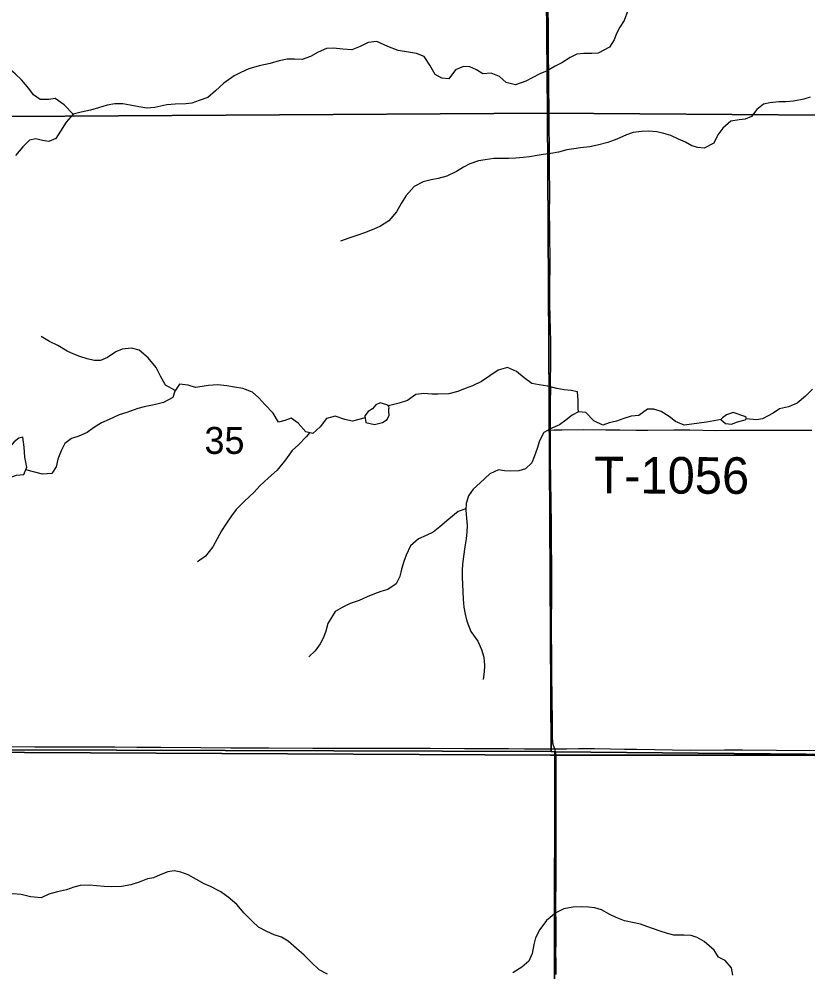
# Model space of a CAD drawing. Extents: x 1874609 to 2204689, y 815661 to 1281160.
# Drawn here: x 2003233 to 2009707, y 1055304 to 1063119 of the extents above; entities that cross this region are included whole.
import ezdxf

# ---------------------------------------------------------------- set-up
doc = ezdxf.new("R2010")
doc.units = 0
for name, color, linetype in [('GM_X_Minor_Lake', 7, 'Continuous'), ('GM_X_Minor_River', 7, 'Continuous'), ('GM_X_Section', 7, 'Continuous'), ('GM_X_Section_Text', 7, 'Continuous'), ('GM_X_Township', 7, 'Continuous'), ('GM_X_Township_Road', 7, 'Continuous'), ('GM_X_Township_Road_Text', 7, 'Continuous')]:
    doc.layers.add(name, color=color, linetype=linetype)

msp = doc.modelspace()

# ---------------------------------------------------------------- linework, layer by layer
at = {"layer": 'GM_X_Minor_Lake'}
for points in [[(2006250.7, 1059956.6), (2006196.4, 1059970.3), (2006160.4, 1059956), (2006132.6, 1059923.6), (2006098.7, 1059901.3), (2006070.9, 1059865), (2006079.4, 1059810.8), (2006149.7, 1059795.3), (2006215.8, 1059809.9), (2006253.7, 1059836.2), (2006269.5, 1059870.5), (2006269.2, 1059900.6)], [(2006269.2, 1059900.6), (2006267.5, 1059921.5), (2006269.5, 1059931.6), (2006268.5, 1059941.8), (2006262.4, 1059950.4), (2006250.7, 1059956.6)], [(2009190.1, 1059860.1), (2009093.6, 1059891.4), (2009037.6, 1059873), (2009005.7, 1059848.6), (2008993.7, 1059834.5), (2009030.1, 1059802.7), (2009080.3, 1059797), (2009128.3, 1059815.4), (2009192.4, 1059832)], [(2009192.4, 1059832), (2009200.8, 1059839.4), (2009201.1, 1059845.6), (2009200.1, 1059850.8), (2009190.1, 1059860.1)], [(2003061.7, 1059315.1), (2003136.6, 1059351.4), (2003212.6, 1059378), (2003272.7, 1059384.5), (2003298.3, 1059444.9), (2003279.5, 1059527.1), (2003274.9, 1059607.3), (2003264.2, 1059689.6), (2003232.1, 1059681.3), (2003194.2, 1059652.9), (2003160.5, 1059612.5), (2003094.2, 1059559.3), (2003053.8, 1059537.5)]]:
    msp.add_lwpolyline(points, dxfattribs=at)
at = {"layer": 'GM_X_Minor_River'}
for points in [[(2008229.8, 1063189), (2008200.4, 1063108.5), (2008164.7, 1063052), (2008137.1, 1063001.6), (2008117.4, 1062949.3), (2008077.8, 1062888.8), (2007986, 1062839.9), (2007933.8, 1062837.5), (2007867.6, 1062837), (2007809.5, 1062832.6), (2007755.6, 1062804.1), (2007687.7, 1062761.4), (2007631.8, 1062732.9), (2007567.9, 1062694.3), (2007508, 1062669.8), (2007444, 1062637.2), (2007392.1, 1062610.7), (2007306.1, 1062579.9), (2007231.7, 1062599.5), (2007175.2, 1062649.2), (2007108.7, 1062676.8), (2007038.6, 1062670.3), (2006986.1, 1062704), (2006931.8, 1062727.7), (2006879.6, 1062731.3), (2006815.6, 1062702.8), (2006760.1, 1062630.1), (2006703.9, 1062633.7), (2006647.5, 1062663.4), (2006604.7, 1062741.3), (2006558, 1062813.2), (2006495.6, 1062836.9), (2006429.3, 1062848.4), (2006344.9, 1062861.8), (2006258.4, 1062893.3), (2006169.8, 1062934.8), (2006097.7, 1062928.3), (2006031.8, 1062893.6), (2005963.8, 1062867), (2005889.5, 1062872.5), (2005813.2, 1062882), (2005757.1, 1062877.6), (2005689.2, 1062846.9), (2005625.2, 1062812.3), (2005557.2, 1062787.8), (2005495, 1062791.3), (2005432.9, 1062790.8), (2005366.8, 1062776.3), (2005294.7, 1062755.7), (2005202.6, 1062734.9), (2005118.6, 1062712.2), (2005052.6, 1062681.6), (2004998.7, 1062653.1), (2004915, 1062594.3), (2004845.3, 1062529.6), (2004781.5, 1062476.9), (2004711.6, 1062450.3), (2004651.6, 1062429.8), (2004601.4, 1062425.4), (2004515.2, 1062420.7), (2004447.1, 1062416.2), (2004346.9, 1062395.4), (2004280.8, 1062388.9), (2004216.5, 1062400.4), (2004146.2, 1062413.9), (2004083.9, 1062423.5), (2004019.7, 1062423.1), (2003955.6, 1062412.5), (2003885.6, 1062391.9), (2003819.6, 1062371.4), (2003743.5, 1062356.8), (2003677.4, 1062340.2), (2003619.8, 1062273.5), (2003574.3, 1062200.9), (2003534.7, 1062140.4), (2003476.7, 1062113.9), (2003424.5, 1062123.6), (2003370.2, 1062137.2), (2003318.1, 1062126.8), (2003264.5, 1062070.2), (2003204.9, 1061999.5)], [(2003677.4, 1062340.2), (2003604.6, 1062415.9), (2003529.9, 1062467.6), (2003477.9, 1062459.2), (2003407.7, 1062458.6), (2003351.2, 1062498.4), (2003314.6, 1062550.3), (2003253.9, 1062620.1), (2003201.3, 1062669.9), (2003142.7, 1062719.6), (2003064.2, 1062755.2)], [(2009726.1, 1062479.5), (2009674, 1062463), (2009589.9, 1062446.3), (2009525.8, 1062441.9), (2009469.6, 1062439.4), (2009395.5, 1062432.9), (2009341.4, 1062420.4), (2009287.6, 1062377.9), (2009244, 1062319.3), (2009192, 1062298.9), (2009141.9, 1062292.5), (2009075.8, 1062282), (2009008, 1062225.3), (2008968.4, 1062168.8), (2008934.8, 1062102.3), (2008855, 1062059.5), (2008804.8, 1062065.2), (2008754.5, 1062080.9), (2008702.1, 1062108.6), (2008645.7, 1062134.2), (2008581.3, 1062163.9), (2008525, 1062181.5), (2008466.7, 1062195.1), (2008398.5, 1062198.7), (2008340.3, 1062198.2), (2008272.2, 1062187.7), (2008218.2, 1062169.2), (2008138.2, 1062134.5), (2008064.2, 1062107.9), (2007980.2, 1062085.1), (2007916.1, 1062072.6), (2007842, 1062062), (2007785.9, 1062055.6), (2007729.8, 1062047.2), (2007659.7, 1062028.6), (2007597.6, 1062016.1), (2007535.5, 1062007.6), (2007485.4, 1061999.2), (2007421.3, 1061988.7), (2007371.2, 1061984.3), (2007309.1, 1061977.8), (2007248.9, 1061975.3), (2007184.7, 1061974.9), (2007128.6, 1061976.5), (2007058.4, 1061965.9), (2007004.4, 1061955.5), (2006932.4, 1061930.8), (2006880.4, 1061904.4), (2006822.5, 1061869.8), (2006744.6, 1061831.1), (2006672.6, 1061812.5), (2006616.5, 1061802), (2006548.5, 1061783.5), (2006476.6, 1061744.8), (2006409, 1061672), (2006369.4, 1061607.5), (2006329.8, 1061539), (2006268.3, 1061464.2), (2006200.5, 1061419.6), (2006144.5, 1061395.1), (2006068.5, 1061366.4), (2006004.5, 1061343.9), (2005938.5, 1061323.3)], [(2005938.5, 1061323.3), (2005872.5, 1061296.7)], [(2004515.5, 1060072.5), (2004434, 1060117.8), (2004393.3, 1060189.7), (2004358.6, 1060261.7), (2004293.8, 1060339.5), (2004219, 1060403.2), (2004156.7, 1060420.8), (2004080.6, 1060412.2), (2004026.6, 1060389.7), (2003958.8, 1060343.1), (2003902.8, 1060318.6), (2003850.7, 1060318.2), (2003792.4, 1060333.8), (2003732, 1060351.4), (2003681.7, 1060371.1), (2003629.4, 1060396.8), (2003552.8, 1060442.4), (2003484.3, 1060476), (2003413.7, 1060515.6)], [(2007823.8, 1059898.1), (2007821.5, 1059928.2), (2007821, 1059990.4), (2007816.4, 1060060.6), (2007764.2, 1060072.3), (2007706, 1060077.9), (2007645.7, 1060089.5), (2007573.3, 1060107), (2007501, 1060120.5), (2007442.7, 1060130.1), (2007378.2, 1060175.8), (2007315.6, 1060229.5), (2007241.1, 1060261.1), (2007165, 1060238.4), (2007097.2, 1060191.8), (2007029.4, 1060147.1), (2006955.5, 1060110.4), (2006895.5, 1060089.9), (2006833.5, 1060063.3), (2006759.4, 1060046.8), (2006671.2, 1060044.1), (2006621.1, 1060043.7), (2006554.8, 1060047.2), (2006490.7, 1060038.7), (2006420.9, 1059992), (2006352.9, 1059969.4), (2006264.5, 1059947.4)], [(2006073.7, 1059847.5), (2005971, 1059820.1), (2005906.7, 1059833.7), (2005826.2, 1059863.2), (2005756.2, 1059842.6), (2005704.6, 1059773.9), (2005642.9, 1059721.3), (2005586.6, 1059734.9), (2005523.8, 1059804.7), (2005465.3, 1059846.4), (2005413.3, 1059828), (2005363.3, 1059813.6), (2005318.5, 1059887.5), (2005249.7, 1059959.2), (2005201.1, 1060013.1), (2005148.6, 1060058.9), (2005070.1, 1060088.4), (2005001.8, 1060099.9), (2004939.6, 1060111.5), (2004863.3, 1060119), (2004789.1, 1060114.4), (2004737, 1060106), (2004680.9, 1060097.5), (2004620.6, 1060117.2), (2004550.3, 1060124.7), (2004512.7, 1060068.2), (2004495.1, 1060015.8), (2004419.2, 1059973.1), (2004341.1, 1059956.5), (2004261, 1059939.8), (2004207, 1059925.4), (2004117, 1059892.6), (2004055, 1059872.1), (2003973, 1059835.3), (2003911.1, 1059806.8), (2003845.2, 1059766.1), (2003793.4, 1059729.6), (2003723.4, 1059697), (2003663.4, 1059678.5), (2003609.6, 1059637.9), (2003578, 1059577.5), (2003552.5, 1059509), (2003537, 1059446.7), (2003501.3, 1059392.2), (2003425.1, 1059385.6), (2003288.9, 1059422.8)], [(2009743.9, 1060083), (2009686.2, 1060026.3), (2009618.5, 1059969.6), (2009546.5, 1059939), (2009474.4, 1059922.4), (2009422.6, 1059885.9), (2009334.7, 1059839.1), (2009284.6, 1059832.7), (2009200.9, 1059841.2)], [(2008994.1, 1059834.9), (2008873.6, 1059813.5), (2008753.4, 1059796.6), (2008691.2, 1059788.1), (2008620.8, 1059817.7), (2008568.3, 1059859.4), (2008503.8, 1059901.1), (2008441.4, 1059920.7), (2008391.3, 1059920.4), (2008319.5, 1059867.6), (2008257.4, 1059863.2), (2008195.3, 1059842.6), (2008137.4, 1059820.1), (2008077.3, 1059807.6), (2008023.3, 1059787.2), (2007950.8, 1059824.8), (2007884, 1059892.5), (2007823.8, 1059898.1), (2007771.9, 1059871.6), (2007720.1, 1059829.1), (2007668.2, 1059790.5), (2007610.3, 1059766), (2007540.4, 1059727.4), (2007504.8, 1059660.9), (2007485.3, 1059596.5), (2007461.8, 1059530.1), (2007442.1, 1059479.7), (2007388.4, 1059429.1), (2007334.4, 1059412.7), (2007270.2, 1059410.2), (2007218, 1059413.8), (2007167.8, 1059421.5), (2007097.9, 1059388.8), (2007016.2, 1059316), (2006960.5, 1059263.4), (2006920.8, 1059208.9), (2006903.3, 1059146.5), (2006899.8, 1059090.3), (2006906.3, 1059026.1), (2006910.8, 1058965.9), (2006909.2, 1058913.7), (2006901.7, 1058857.5), (2006892.2, 1058789.2), (2006880.8, 1058710.8), (2006873.3, 1058648.5), (2006869.8, 1058596.3), (2006870.2, 1058538.1), (2006872.7, 1058481.9), (2006875.2, 1058423.7), (2006877.7, 1058361.5), (2006884.3, 1058295.3), (2006894.8, 1058239.2), (2006907.3, 1058181.1), (2006940.1, 1058095), (2006998.9, 1058017.1), (2007029.6, 1057949.1), (2007048.2, 1057885), (2007052.7, 1057816.8), (2007051.2, 1057766.6), (2007041.7, 1057702.3)], [(2005618.3, 1059727.2), (2005588.9, 1059692.8), (2005525.3, 1059628.1), (2005473.5, 1059579.5), (2005420, 1059504.8), (2005350.5, 1059420), (2005280.8, 1059357.3), (2005209.2, 1059290.5), (2005161.4, 1059240), (2005083.8, 1059165.1), (2005016.2, 1059096.4), (2004976.5, 1059045.9), (2004928.9, 1058977.3), (2004895.3, 1058922.8), (2004859.7, 1058856.3), (2004824.1, 1058791.8), (2004762.6, 1058713.1), (2004696.8, 1058668.4)], [(2006900.5, 1059102.2), (2006837.7, 1059079.8), (2006760, 1059017), (2006686.3, 1058954.2), (2006630.4, 1058911.7), (2006574.5, 1058883.1), (2006512.6, 1058856.6), (2006446.8, 1058799.9), (2006409.4, 1058723.3), (2006389.7, 1058669), (2006372.2, 1058606.6), (2006358.7, 1058548.3), (2006329.1, 1058487.9), (2006259.3, 1058441.2), (2006203.2, 1058424.7), (2006151.2, 1058404.3), (2006091.3, 1058379.7), (2006023.3, 1058351.1), (2005949.3, 1058326.5), (2005885.4, 1058291.9), (2005827.5, 1058261.3), (2005766.1, 1058162.5), (2005750.6, 1058098.2), (2005733, 1058045.9), (2005703.3, 1057995.4), (2005663.7, 1057936.9), (2005611.9, 1057888.4)], [(2005765.9, 1055286), (2005695.4, 1055321.6), (2005628.7, 1055385.4), (2005574.1, 1055441.2), (2005509.4, 1055496.9), (2005442.7, 1055556.6), (2005386.3, 1055588.3), (2005326, 1055608), (2005267.6, 1055635.6), (2005199.1, 1055671.2), (2005148.5, 1055717), (2005081.8, 1055784.8), (2005021, 1055856.6), (2004950.3, 1055918.3), (2004889.8, 1055960), (2004803.2, 1056003.5), (2004752.8, 1056025.2), (2004690.3, 1056062.9), (2004621.8, 1056100.5), (2004561.5, 1056122.2), (2004505.2, 1056133.8), (2004455.1, 1056125.4), (2004391.2, 1056100.8), (2004337.2, 1056074.3), (2004287.1, 1056067.9), (2004219.1, 1056041.3), (2004151.1, 1056018.8), (2004075, 1056004.1), (2003994.8, 1056001.5), (2003930.6, 1056005.1), (2003868.4, 1056010.6), (2003810.2, 1056014.2), (2003734, 1056011.6), (2003681.9, 1055999.2)], [(2003681.9, 1055999.2), (2003623.9, 1055976.7), (2003549.9, 1055960.1), (2003477.8, 1055941.5), (2003413.9, 1055912.9), (2003327.5, 1055920.3), (2003251.2, 1055937.8), (2003182.9, 1055943.3), (2003110.8, 1055938.7)], [(2009091.7, 1055278.6), (2009081.2, 1055336.8), (2009028.5, 1055396.6), (2008972.1, 1055424.3), (2008937.6, 1055482.2), (2008854.7, 1055553.9), (2008798.3, 1055585.6), (2008748, 1055603.3), (2008691.8, 1055604.9), (2008605.6, 1055606.2), (2008555.3, 1055617.9), (2008495, 1055637.5), (2008438.7, 1055657.2), (2008384.3, 1055676.9), (2008334, 1055694.6), (2008281.8, 1055706.2), (2008201.4, 1055723.7), (2008133, 1055751.3), (2008080.6, 1055775), (2008014.1, 1055812.6), (2007957.8, 1055830.3), (2007905.6, 1055835.9), (2007847.4, 1055837.5), (2007777.3, 1055834.9), (2007705.2, 1055820.3), (2007637.2, 1055789.7), (2007561.5, 1055726.9), (2007508, 1055652.3), (2007472.4, 1055583.8), (2007458.9, 1055527.5), (2007445.4, 1055455.1), (2007417.9, 1055392.7), (2007358.1, 1055342), (2007286.3, 1055295.3)]]:
    msp.add_lwpolyline(points, dxfattribs=at)
at = {"layer": 'GM_X_Section'}
for points in [[(2012811.7, 1067655.4), (2012875, 1062308.6), (2007570, 1062347.4), (2007522.5, 1067772.3), (2008728.9, 1067827.5), (2010105.8, 1067848.3), (2011337.2, 1067789)], [(2007522.5, 1067772.3), (2007570, 1062347.4), (2002286.6, 1062314.1), (2002208.8, 1067736.9)], [(2007570, 1062347.4), (2007601.1, 1057110.7), (2002246.1, 1057127.3), (2002286.6, 1062314.1)], [(2012875, 1062308.6), (2012928.1, 1057059.8), (2007629.1, 1057108.7), (2007601.1, 1057110.7), (2007570, 1062347.4)], [(2002232.1, 1057127.3), (2002246.1, 1057127.3), (2007601.1, 1057110.7), (2007629.1, 1057108.7), (2007622.1, 1051897.9), (2002195.7, 1051966.5)], [(2012928.1, 1057059.8), (2012905.1, 1051801), (2007622.1, 1051897.9), (2007629.1, 1057108.7)]]:
    msp.add_lwpolyline(points, close=True, dxfattribs=at)
at = {"layer": 'GM_X_Township'}
for points in [[(2012701.4, 1077595.4), (2012822.6, 1068444.9), (2012815.7, 1067541.2), (2012879.9, 1063357.3), (2012876.9, 1060382), (2012922.1, 1057082.7), (2007594.7, 1057081.4), (2002196.8, 1057110.3), (1999576.7, 1057105.3), (1994308.2, 1057091.3), (1992170.2, 1057095), (1991695.7, 1057095.3), (1991547.4, 1057096), (1991530.2, 1062399.9), (1991512.8, 1067770.2), (1991419.1, 1075774.5), (1991355.2, 1080411.9)], [(1991697.2, 1052019), (1991696, 1055882.4), (1991695.9, 1056162.5), (1991695.7, 1057095.3), (1992170.2, 1057095), (1994308.2, 1057091.3), (1999576.7, 1057105.3), (2002196.8, 1057110.3), (2007594.7, 1057081.4), (2012922.1, 1057082.7), (2012924.9, 1056002.2), (2012935.3, 1053679.3)]]:
    msp.add_lwpolyline(points, dxfattribs=at)
at = {"layer": 'GM_X_Township_Road'}
for points in [[(2007595.6, 1059748.8), (2007595, 1059909.2), (2007595.8, 1060007.6), (2007596.3, 1060056.6), (2007595.2, 1060155), (2007597, 1060286.2), (2007597, 1060368.2), (2007597.1, 1060417.3), (2007597.1, 1060466.3), (2007593.9, 1060580.7), (2007591.8, 1060662.5), (2007591.1, 1060678.9), (2007590.8, 1060711.7), (2007590.3, 1060744.4), (2007589.4, 1060809.9), (2007589.6, 1060941.1), (2007590.5, 1061088.8), (2007589, 1061400.5), (2007587, 1061531.8), (2007588.4, 1061663), (2007585.1, 1061925.5), (2007585.1, 1062040.3), (2007583.7, 1062270.1), (2007583.2, 1062401.3), (2007581.7, 1062532.4), (2007579.8, 1062647.2), (2007577.5, 1062844), (2007577.3, 1063008.1), (2007575.4, 1063254.3)], [(2007628.9, 1057134.1), (2007624.5, 1057146.8), (2007618.5, 1057161.7), (2007614.8, 1057179.5), (2007610.4, 1057239.1), (2007610.7, 1057370), (2007609.4, 1057533.7), (2007605.7, 1057763.3), (2007605.4, 1057828.9), (2007605.7, 1057878), (2007605.2, 1057943.5), (2007604.1, 1058040.1), (2007604.1, 1058092.9), (2007604.1, 1058165.6), (2007604.1, 1058236.5), (2007604.6, 1058318.6), (2007605.6, 1058564.7), (2007605.4, 1058646.6), (2007603.8, 1058810.4), (2007601.8, 1058990.7), (2007599.2, 1059138.3), (2007597.9, 1059351.6), (2007594.7, 1059499.1), (2007594.9, 1059613.9), (2007595.6, 1059728.7), (2007595.6, 1059748.8)], [(2007595.6, 1059748.8), (2007623.8, 1059749), (2007688.6, 1059749.5), (2007869, 1059751.7), (2008049.4, 1059750.6), (2008164.2, 1059749.9), (2008295.3, 1059748.6), (2008393.7, 1059748), (2008607, 1059749.6), (2008738.1, 1059749.8), (2008951.3, 1059745.7), (2009066.2, 1059746.6), (2009328.6, 1059747.4), (2009525.4, 1059748), (2009738.6, 1059747.8)], [(2002804.3, 1057156.9), (2003362.3, 1057151.2), (2003460.6, 1057150.1), (2003772.4, 1057150.5), (2004018.6, 1057149.4), (2004199.1, 1057148.1), (2004396, 1057146), (2004724.2, 1057144.7), (2004970.4, 1057142.5), (2005282.2, 1057141.6), (2005643.2, 1057140), (2005823.7, 1057139.9), (2005987.7, 1057138), (2006200.7, 1057138.6), (2006364.8, 1057139.2), (2006611, 1057139.6), (2006889.9, 1057136.7), (2007119.6, 1057136.4), (2007251, 1057135.5), (2007382.2, 1057134.1), (2007497.1, 1057133.5), (2007606.9, 1057134), (2007628.9, 1057134.1)], [(2007628.9, 1057134.1), (2007726.5, 1057134.7), (2007825, 1057135.5), (2007956.3, 1057136.1), (2008087.6, 1057134.6), (2008202.3, 1057132.2), (2008300.7, 1057130.7), (2008596, 1057125.4), (2008743.6, 1057123.9), (2009022.5, 1057124.8), (2009170.2, 1057124.3), (2009448.8, 1057122.7), (2009809.5, 1057120.5)], [(2007641.2, 1055283.6), (2007640.2, 1055381.4), (2007639.7, 1055462.8), (2007639.8, 1055544.6), (2007640.7, 1055643.1), (2007639.8, 1055725.2), (2007638.8, 1055790.9), (2007638.2, 1055872.6), (2007639.3, 1055905.2), (2007640, 1056018.8), (2007640.4, 1056084), (2007640.9, 1056133.3), (2007641.5, 1056231.6), (2007640.6, 1056330.1), (2007641.3, 1056362.9), (2007641.5, 1056444.7), (2007641.2, 1056493.9), (2007641.4, 1056526.6), (2007641.6, 1056591.9), (2007640.7, 1056657.5), (2007641.2, 1056706.5), (2007641.2, 1056853.3), (2007640.9, 1056951.7), (2007640.7, 1057033.7), (2007640.2, 1057066.3), (2007640.8, 1057082.1), (2007638.6, 1057101.4), (2007628.9, 1057134.1)]]:
    msp.add_lwpolyline(points, dxfattribs=at)

# ---------------------------------------------------------------- texts
at = {"layer": 'GM_X_Section_Text'}
msp.add_text('35', height=221, rotation=0.00001, dxfattribs=at).set_placement((2004754.6, 1059552.8))
at = {"layer": 'GM_X_Township_Road_Text'}
msp.add_text('T-1056', height=300, rotation=359.76574, dxfattribs=at).set_placement((2007953.3, 1059229.8))

doc.saveas('drawing.dxf')
